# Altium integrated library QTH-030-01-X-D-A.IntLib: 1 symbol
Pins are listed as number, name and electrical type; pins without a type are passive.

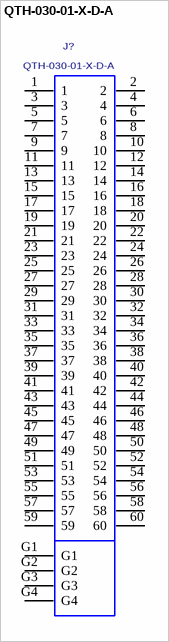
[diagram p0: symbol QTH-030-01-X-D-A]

## QTH-030-01-X-D-A
designator J?
HIGH SPEED TERMINAL STRIP, .5mm PITCH, 60 PINS.; MANUFACTURER: SAMTEC
footprint QTH-030-01-X-D-A
pins: 1, 2, 3, 4, 5, 6, 7, 8, 9, 10, 11, 12, 13, 14, 15, 16, 17, 18, 19, 20, 21, 22, 23, 24, 25, 26, 27, 28, 29, 30, 31, 32, 33, 34, 35, 36, 37, 38, 39, 40, 41, 42, 43, 44, 45, 46, 47, 48, 49, 50, 51, 52, 53, 54, 55, 56, 57, 58, 59, 60, G1, G2, G3, G4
